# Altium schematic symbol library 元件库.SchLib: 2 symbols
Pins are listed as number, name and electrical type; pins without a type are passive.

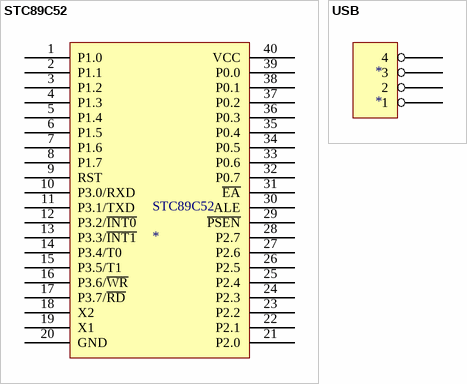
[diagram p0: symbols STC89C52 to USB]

## STC89C52
designator STC89C52
pins: 1 P1.0, 2 P1.1, 3 P1.2, 4 P1.3, 5 P1.4, 6 P1.5, 7 P1.6, 8 P1.7, 9 RST, 10 P3.0/RXD, 11 P3.1/TXD, 12 P3.2/~{INT0}, 13 P3.3/~{INT1}, 14 P3.4/T0, 15 P3.5/T1, 16 P3.6/~{WR}, 17 P3.7/~{RD}, 18 X2, 19 X1, 20 GND, 21 P2.0, 22 P2.1, 23 P2.2, 24 P2.3, 25 P2.4, 26 P2.5, 27 P2.6, 28 P2.7, 29 ~{PSEN}, 30 ALE, 31 ~{EA}, 32 P0.7, 33 P0.6, 34 P0.5, 35 P0.4, 36 P0.3, 37 P0.2, 38 P0.1, 39 P0.0, 40 VCC

## USB
designator *
pins: ?1 1, ?2 2, ?3 3, ?4 4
